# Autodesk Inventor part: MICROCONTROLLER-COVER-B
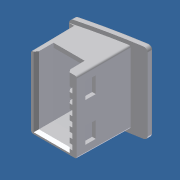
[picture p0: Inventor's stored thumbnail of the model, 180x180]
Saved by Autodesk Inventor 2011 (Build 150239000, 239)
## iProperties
Created: 2008-01
Part Number: MICROCONTROLLER-COVER-B
Document SubType Name: Modeling
Density: 1 g/cm^3
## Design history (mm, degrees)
feature "Base1"
body "Solid1"
